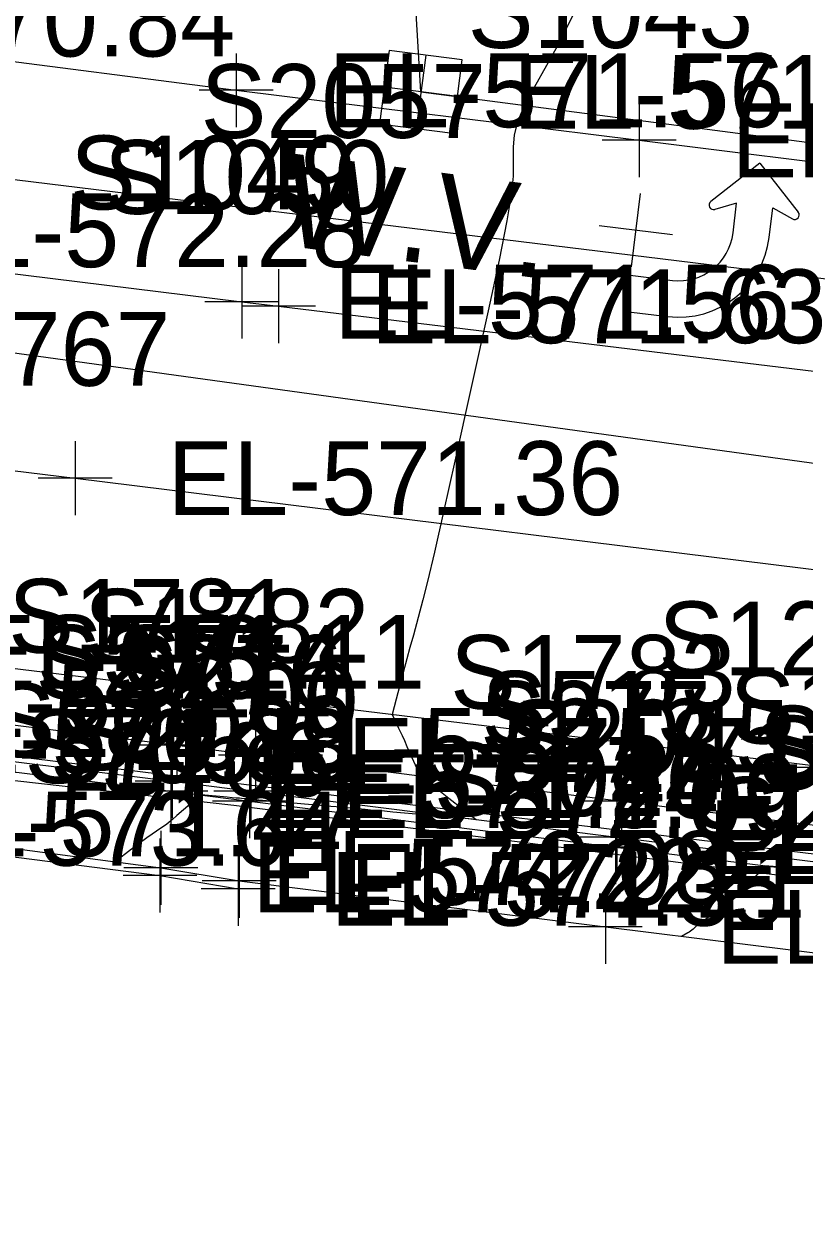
# Model space of a CAD drawing. Extents: x 1724534 to 1727318, y 657156 to 660047.
# Drawn here: x 1725826.2 to 1725868.5, y 658518.4 to 658583.4 of the extents above; entities that cross this region are included whole.
import ezdxf

# ---------------------------------------------------------------- set-up
doc = ezdxf.new("R2010")
doc.units = 0
for name, color, linetype in [('SURVEY - CONTOURS - Intermediate with optional Text', 7, 'Continuous'), ('SURVEY - DRAINAGE - Area Shapes', 7, 'Continuous'), ('SURVEY - DRAINAGE - Storm Sewer', 7, 'Continuous'), ('SURVEY - DRAINAGE - Storm Sewer - Points - Numbers', 7, 'Continuous'), ('SURVEY - DTM - Breaklines', 7, 'Continuous'), ('SURVEY - DTM - Breaklines - Points - Elevations', 7, 'Continuous'), ('SURVEY - DTM - Breaklines - Points - Locators', 7, 'Continuous'), ('SURVEY - DTM - Breaklines - Points - Numbers', 7, 'Continuous'), ('SURVEY - ROADSIDE BARRIERS - Points - Elevations', 7, 'Continuous'), ('SURVEY - ROADSIDE BARRIERS - Points - Locators', 7, 'Continuous'), ('SURVEY - ROADSIDE BARRIERS - Points - Numbers', 7, 'Continuous'), ('SURVEY - ROADSIDE BARRIERS with Text', 7, 'Continuous'), ('SURVEY - TRAFFIC CONTROL - Pavement Marking - Points - Elevations', 7, 'Continuous'), ('SURVEY - TRAFFIC CONTROL - Pavement Marking - Points - Locators', 7, 'Continuous'), ('SURVEY - TRAFFIC CONTROL - Pavement Marking - Points - Numbers', 7, 'Continuous'), ('SURVEY - TRAFFIC CONTROL - Pavement Marking with Text', 7, 'Continuous'), ('SURVEY - TRANSPORTATION - Features', 7, 'Continuous'), ('SURVEY - TRANSPORTATION - Features - Points - Elevations', 7, 'Continuous'), ('SURVEY - TRANSPORTATION - Features - Points - Locators', 7, 'Continuous'), ('SURVEY - TRANSPORTATION - Features - Points - Numbers', 7, 'Continuous'), ('SURVEY - TRANSPORTATION - Roads', 7, 'Continuous'), ('SURVEY - TRANSPORTATION - Roads - Points - Elevations', 7, 'Continuous'), ('SURVEY - TRANSPORTATION - Roads - Points - Locators', 7, 'Continuous'), ('SURVEY - TRANSPORTATION - Roads - Points - Numbers', 7, 'Continuous'), ('SURVEY - UTILITIES - Electric (Underground) with Text', 7, 'Continuous'), ('SURVEY - UTILITIES - Water - Points - Elevations', 7, 'Continuous'), ('SURVEY - UTILITIES - Water - Points - Locators', 7, 'Continuous'), ('SURVEY - UTILITIES - Water with Text', 7, 'Continuous')]:
    doc.layers.add(name, color=color, linetype=linetype)

msp = doc.modelspace()

# ---------------------------------------------------------------- linework, layer by layer
at = {"layer": 'SURVEY - CONTOURS - Intermediate with optional Text'}
for points in [[(1725855.954, 658583.868), (1725855.595, 658583.124), (1725855.203, 658582.364), (1725854.778, 658581.589), (1725853.601, 658579.503), (1725853.215, 658578.743), (1725852.939, 658578.03), (1725852.773, 658577.363), (1725852.717, 658576.741), (1725852.714, 658575.145), (1725852.629, 658574.241), (1725852.375, 658572.723), (1725851.952, 658570.593), (1725851.361, 658567.85), (1725849.559, 658559.717), (1725848.944, 658556.96), (1725848.449, 658554.786), (1725848.076, 658553.196), (1725847.823, 658552.19), (1725847.31, 658550.285), (1725847.128, 658549.606), (1725846.964, 658548.998), (1725846.695, 658547.996), (1725846.155, 658545.991), (1725846.509, 658545.252), (1725846.595, 658545.071), (1725846.699, 658544.844), (1725846.822, 658544.572), (1725846.965, 658544.254), (1725847.672, 658542.666), (1725848.318, 658542.163), (1725848.478, 658542.038), (1725848.684, 658541.878), (1725849.229, 658541.453), (1725850.711, 658540.3), (1725849.502, 658540.407), (1725849.265, 658540.428), (1725849.07, 658540.446), (1725848.811, 658540.469), (1725848.581, 658540.489), (1725848.446, 658540.501), (1725848.214, 658540.522), (1725847.884, 658540.551), (1725846.192, 658540.702), (1725845.743, 658540.742), (1725845.344, 658540.778), (1725844.995, 658540.809), (1725844.698, 658540.836), (1725843.697, 658540.925), (1725843.418, 658540.95), (1725843.134, 658540.976), (1725842.846, 658541.001), (1725842.073, 658541.07), (1725841.409, 658541.13), (1725841.014, 658541.165), (1725840.578, 658541.204), (1725839.359, 658541.314), (1725838.948, 658541.351), (1725838.397, 658541.4), (1725838.257, 658541.413), (1725838.007, 658541.435), (1725837.887, 658541.446), (1725837.715, 658541.461), (1725837.491, 658541.48), (1725837.216, 658541.504), (1725835.808, 658541.627), (1725834.5, 658540.513), (1725834.254, 658540.304), (1725834.079, 658540.154), (1725833.939, 658540.035), (1725833.939, 658540.035), (1725833.91, 658540.015), (1725833.824, 658539.956), (1725833.681, 658539.859), (1725832.871, 658539.305), (1725832.647, 658539.15), (1725832.433, 658538.996), (1725832.228, 658538.845), (1725832.034, 658538.696), (1725831.149, 658538.004), (1725831.129, 658537.971)], [(1725868.725, 658537.589), (1725868.398, 658537.617), (1725868.173, 658537.636), (1725868.049, 658537.646), (1725867.766, 658537.67), (1725867.643, 658537.681), (1725867.485, 658537.694), (1725867.294, 658537.711), (1725866.324, 658537.794), (1725865.387, 658536.685), (1725865.169, 658536.448), (1725864.919, 658536.21), (1725864.636, 658535.973), (1725864.32, 658535.735), (1725863.434, 658535.102), (1725863.135, 658534.887), (1725862.903, 658534.717), (1725862.737, 658534.592), (1725862.639, 658534.512), (1725862.465, 658534.357), (1725862.399, 658534.301), (1725862.331, 658534.25), (1725862.26, 658534.202), (1725862.188, 658534.159), (1725861.845, 658533.968)]]:
    msp.add_lwpolyline(points, dxfattribs=at)
at = {"layer": 'SURVEY - DRAINAGE - Area Shapes'}
msp.add_lwpolyline([(1725876.527, 658537.521), (1725880.453, 658568.253), (1725462.782, 658619.36), (1725459.014, 658588.567)], close=True, dxfattribs=at)
at = {"layer": 'SURVEY - DRAINAGE - Storm Sewer'}
msp.add_lwpolyline([(1725899.594, 658555.371), (1725464.565, 658615.304), (1725129.381, 658652.795)], dxfattribs=at)
at = {"layer": 'SURVEY - DTM - Breaklines'}
msp.add_lwpolyline([(1725680.682, 658560.757), (1725700.532, 658558.327), (1725720.383, 658555.896), (1725740.231, 658553.451), (1725761.261, 658550.794), (1725763.358, 658550.522), (1725772.397, 658549.361), (1725785.767, 658547.812), (1725794.485, 658546.715), (1725814.329, 658544.278), (1725834.171, 658541.836), (1725838.432, 658541.293), (1725858.267, 658538.797), (1725873.4, 658536.913), (1725878.358, 658536.288), (1725898.186, 658533.731), (1725916.254, 658531.264)], dxfattribs=at)
at = {"layer": 'SURVEY - DTM - Breaklines - Points - Locators'}
for p, q in [((1725834.171, 658543.836), (1725834.171, 658539.836)), ((1725838.432, 658543.293), (1725838.432, 658539.293)), ((1725836.171, 658541.836), (1725832.171, 658541.836)), ((1725840.432, 658541.293), (1725836.432, 658541.293)), ((1725858.267, 658540.797), (1725858.267, 658536.797)), ((1725860.267, 658538.797), (1725856.267, 658538.797))]:
    msp.add_line(p, q, dxfattribs=at)
at = {"layer": 'SURVEY - ROADSIDE BARRIERS - Points - Locators'}
for p, q in [((1725833.582, 658539.268), (1725833.582, 658535.268)), ((1725837.82, 658538.545), (1725837.82, 658534.545)), ((1725835.582, 658537.268), (1725831.582, 658537.268)), ((1725839.82, 658536.545), (1725835.82, 658536.545))]:
    msp.add_line(p, q, dxfattribs=at)
at = {"layer": 'SURVEY - ROADSIDE BARRIERS with Text'}
msp.add_lwpolyline([(1725760.694, 658546.317), (1725762.794, 658546.074), (1725771.84, 658544.972), (1725785.195, 658543.377), (1725793.917, 658542.307), (1725813.751, 658539.797), (1725833.582, 658537.268), (1725837.82, 658536.545)], dxfattribs=at)
at = {"layer": 'SURVEY - TRAFFIC CONTROL - Pavement Marking - Points - Locators'}
for p, q in [((1725837.716, 658581.798), (1725837.716, 658577.798)), ((1725839.716, 658579.798), (1725835.716, 658579.798)), ((1725859.541, 658579.092), (1725859.541, 658575.092)), ((1725861.541, 658577.092), (1725857.541, 658577.092)), ((1725859.603, 658574.204), (1725859.117, 658570.234)), ((1725861.345, 658571.976), (1725857.375, 658572.462)), ((1725838.021, 658570.345), (1725838.021, 658566.345)), ((1725840.005, 658570.1), (1725840.005, 658566.1)), ((1725840.021, 658568.345), (1725836.021, 658568.345)), ((1725842.005, 658568.1), (1725838.005, 658568.1)), ((1725828.993, 658560.789), (1725828.993, 658556.789)), ((1725830.993, 658558.789), (1725826.993, 658558.789))]:
    msp.add_line(p, q, dxfattribs=at)
at = {"layer": 'SURVEY - TRAFFIC CONTROL - Pavement Marking with Text'}
for p, q in [((1725866.084, 658575.858), (1725863.423, 658573.777)), ((1725866.084, 658575.858), (1725868.164, 658573.197)), ((1725864.825, 658573.675), (1725863.641, 658573.347)), ((1725864.629, 658572.07), (1725864.825, 658573.675)), ((1725866.582, 658571.831), (1725866.779, 658573.437)), ((1725866.779, 658573.437), (1725867.849, 658572.832)), ((1725859.061, 658569.777), (1725858.822, 658567.824)), ((1725859.061, 658569.777), (1725861.34, 658569.498)), ((1725858.822, 658567.824), (1725861.101, 658567.545))]:
    msp.add_line(p, q, dxfattribs=at)
for points in [[(1725507.893, 658598.435), (1725611.44, 658585.624), (1725663.045, 658579.239), (1725732.511, 658570.646), (1725771.433, 658565.831), (1725828.993, 658558.789), (1725876.604, 658552.91), (1725911.384, 658548.615)], [(1725691.276, 658598.614), (1725717.028, 658595.036), (1725719.009, 658594.766), (1725742.941, 658591.917), (1725766.76, 658588.985), (1725807.969, 658583.629), (1725837.716, 658579.798), (1725859.541, 658577.092), (1725887.31, 658573.624), (1725917.054, 658569.88)], [(1725753.893, 658578.677), (1725768.555, 658576.886), (1725792.375, 658573.977), (1725838.021, 658568.345), (1725840.005, 658568.1), (1725897.548, 658561.116), (1725916.187, 658558.855)]]:
    msp.add_lwpolyline(points, dxfattribs=at)
for centre, radius, start, end in [((1725863.575, 658573.583), 0.246, 128.02638, 285.51954), ((1725867.97, 658573.046), 0.246, 240.57811, 38.02638), ((1725861.699, 658572.429), 4.92, 263.02638, 353.02638), ((1725861.699, 658572.429), 2.952, 263.02638, 353.02638)]:
    msp.add_arc(centre, radius, start, end, dxfattribs=at)
at = {"layer": 'SURVEY - TRANSPORTATION - Features'}
for points in [[(1725680.75, 658561.297), (1725700.601, 658558.867), (1725720.452, 658556.439), (1725740.3, 658553.994), (1725761.33, 658551.338), (1725763.427, 658551.066), (1725772.465, 658549.905), (1725773.017, 658549.841), (1725785.837, 658548.356), (1725794.555, 658547.258), (1725814.399, 658544.822), (1725834.241, 658542.379), (1725838.502, 658541.836), (1725858.338, 658539.34), (1725873.47, 658537.457), (1725878.428, 658536.831), (1725898.256, 658534.275), (1725916.324, 658531.808)], [(1725773.017, 658549.841), (1725772.713, 658551.857), (1725786.089, 658550.308), (1725794.807, 658549.211), (1725814.651, 658546.773), (1725834.493, 658544.331), (1725838.754, 658543.788), (1725858.589, 658541.292), (1725873.721, 658539.408), (1725878.681, 658538.783), (1725898.508, 658536.226), (1725916.581, 658533.801)], [(1725760.676, 658546.181), (1725762.959, 658547.374), (1725771.996, 658546.202), (1725785.261, 658543.884), (1725793.979, 658542.787), (1725813.816, 658540.298), (1725833.635, 658537.675), (1725837.876, 658536.979), (1725857.711, 658534.482), (1725872.844, 658532.599), (1725877.802, 658531.973), (1725897.627, 658529.389), (1725915.695, 658526.927)]]:
    msp.add_lwpolyline(points, dxfattribs=at)
at = {"layer": 'SURVEY - TRANSPORTATION - Features - Points - Locators'}
for p, q in [((1725834.493, 658546.331), (1725834.493, 658542.331)), ((1725838.754, 658545.788), (1725838.754, 658541.788)), ((1725836.493, 658544.331), (1725832.493, 658544.331)), ((1725834.241, 658544.379), (1725834.241, 658540.379)), ((1725840.754, 658543.788), (1725836.754, 658543.788)), ((1725838.502, 658543.836), (1725838.502, 658539.836)), ((1725858.589, 658543.292), (1725858.589, 658539.292)), ((1725836.241, 658542.379), (1725832.241, 658542.379)), ((1725840.502, 658541.836), (1725836.502, 658541.836)), ((1725860.589, 658541.292), (1725856.589, 658541.292)), ((1725858.338, 658541.34), (1725858.338, 658537.34)), ((1725833.635, 658539.675), (1725833.635, 658535.675)), ((1725860.338, 658539.34), (1725856.338, 658539.34)), ((1725837.876, 658538.979), (1725837.876, 658534.979)), ((1725835.635, 658537.675), (1725831.635, 658537.675)), ((1725839.876, 658536.979), (1725835.876, 658536.979)), ((1725857.711, 658536.482), (1725857.711, 658532.482)), ((1725859.711, 658534.482), (1725855.711, 658534.482))]:
    msp.add_line(p, q, dxfattribs=at)
at = {"layer": 'SURVEY - TRANSPORTATION - Roads'}
msp.add_lwpolyline([(1725616.971, 658574.343), (1725730.092, 658560.27), (1725772.626, 658554.978), (1725818.273, 658549.383), (1725869.87, 658543.106), (1725897.655, 658539.757), (1725899.639, 658539.517), (1725928.541, 658535.917)], dxfattribs=at)
at = {"layer": 'SURVEY - TRANSPORTATION - Roads - Points - Locators'}
msp.add_line((1725871.87, 658543.106), (1725867.87, 658543.106), dxfattribs=at)
at = {"layer": 'SURVEY - UTILITIES - Electric (Underground) with Text'}
msp.add_lwpolyline([(1725780.974, 658547.452), (1725837.588, 658541.08), (1725892.762, 658533.99), (1725944.681, 658527.231), (1725958.361, 658525.297), (1725964.566, 658523.411), (1725971.45, 658518.072), (1725975.975, 658512.132)], dxfattribs=at)
at = {"layer": 'SURVEY - UTILITIES - Water - Points - Locators'}
for p, q in [((1725847.98, 658581.696), (1725847.468, 658577.728)), ((1725849.708, 658579.456), (1725845.74, 658579.968))]:
    msp.add_line(p, q, dxfattribs=at)
at = {"layer": 'SURVEY - UTILITIES - Water with Text'}
msp.add_line((1725847.724, 658579.712), (1725847.724, 658579.712), dxfattribs=at)
for points in [[(1725847.724, 658579.712), (1725846.548, 658599.52), (1725380.522, 658660.104)], [(1725845.996, 658581.951), (1725845.485, 658577.984), (1725849.452, 658577.473), (1725849.963, 658581.44), (1725845.996, 658581.951)], [(1725847.724, 658579.712), (1725982.184, 658562.183), (1725988.335, 658559.963), (1726011.571, 658556.88)]]:
    msp.add_lwpolyline(points, dxfattribs=at)

# ---------------------------------------------------------------- texts
at = {"layer": 'SURVEY - DRAINAGE - Storm Sewer - Points - Numbers'}
msp.add_text('S2045', height=4, dxfattribs=at).set_placement((1725852.254, 658542.78))
at = {"layer": 'SURVEY - DTM - Breaklines - Points - Elevations'}
for s, p in [('EL-571.38', (1725819.329, 658542.278)), ('EL-571.94', (1725839.171, 658539.836)), ('EL-572.09', (1725843.432, 658539.293)), ('EL-572.73', (1725863.267, 658536.797))]:
    msp.add_text(s, height=4, dxfattribs=at).set_placement(p)
at = {"layer": 'SURVEY - DTM - Breaklines - Points - Numbers'}
for s, p in [('S275', (1725826.835, 658546.836)), ('S276', (1725830.986, 658546.293)), ('S277', (1725850.931, 658543.797)), ('S278', (1725866.017, 658541.913))]:
    msp.add_text(s, height=4, dxfattribs=at).set_placement(p)
at = {"layer": 'SURVEY - ROADSIDE BARRIERS - Points - Elevations'}
for s, p in [('EL-573.64', (1725818.751, 658537.797)), ('EL-574.22', (1725838.582, 658535.268)), ('EL-574.35', (1725842.82, 658534.545))]:
    msp.add_text(s, height=4, dxfattribs=at).set_placement(p)
at = {"layer": 'SURVEY - ROADSIDE BARRIERS - Points - Numbers'}
for s, p in [('S705', (1725826.246, 658542.268)), ('S706', (1725830.374, 658541.545))]:
    msp.add_text(s, height=4, dxfattribs=at).set_placement(p)
at = {"layer": 'SURVEY - TRAFFIC CONTROL - Pavement Marking - Points - Elevations'}
for s, p in [('EL-570.84', (1725812.969, 658581.629)), ('EL-571.56', (1725842.716, 658577.798)), ('EL-572.20', (1725864.541, 658575.092)), ('EL-572.28', (1725820.075, 658570.219)), ('EL-571.56', (1725843.021, 658566.345)), ('EL-571.63', (1725845.005, 658566.1)), ('EL-571.36', (1725833.993, 658556.789))]:
    msp.add_text(s, height=4, dxfattribs=at).set_placement(p)
at = {"layer": 'SURVEY - TRAFFIC CONTROL - Pavement Marking - Points - Numbers'}
for s, p in [('S1043', (1725850.253, 658582.092)), ('S2057', (1725835.784, 658577.219)), ('S1049', (1725828.718, 658573.345)), ('S1050', (1725830.544, 658573.1)), ('S767', (1725821.657, 658563.789))]:
    msp.add_text(s, height=4, dxfattribs=at).set_placement(p)
at = {"layer": 'SURVEY - TRANSPORTATION - Features - Points - Elevations'}
for s, p in [('EL-571.00', (1725819.651, 658544.773)), ('EL-570.88', (1725819.399, 658542.822)), ('EL-571.58', (1725839.493, 658542.331)), ('EL-571.71', (1725843.754, 658541.788)), ('EL-571.46', (1725839.241, 658540.379)), ('EL-571.60', (1725843.502, 658539.836)), ('EL-572.36', (1725863.589, 658539.292)), ('EL-571.47', (1725819.816, 658538.298)), ('EL-572.25', (1725863.338, 658537.34)), ('EL-572.08', (1725839.635, 658535.675)), ('EL-572.21', (1725843.876, 658534.979)), ('EL-572.89', (1725863.711, 658532.482))]:
    msp.add_text(s, height=4, dxfattribs=at).set_placement(p)
at = {"layer": 'SURVEY - TRANSPORTATION - Features - Points - Numbers'}
for s, p in [('S1781', (1725825.363, 658549.331)), ('S1782', (1725829.466, 658548.788)), ('S513', (1725826.905, 658547.379)), ('S514', (1725831.166, 658546.836)), ('S1783', (1725849.301, 658546.292)), ('S515', (1725851.002, 658544.34)), ('S1784', (1725864.433, 658544.408)), ('S2022', (1725824.347, 658543.675)), ('S2023', (1725828.588, 658542.979)), ('S516', (1725866.024, 658542.457)), ('S2024', (1725848.423, 658540.482)), ('S2025', (1725863.556, 658538.599))]:
    msp.add_text(s, height=4, dxfattribs=at).set_placement(p)
at = {"layer": 'SURVEY - TRANSPORTATION - Roads - Points - Elevations'}
msp.add_text('EL-571.11', height=4, dxfattribs=at).set_placement((1725823.273, 658547.383))
at = {"layer": 'SURVEY - TRANSPORTATION - Roads - Points - Numbers'}
msp.add_text('S1284', height=4, dxfattribs=at).set_placement((1725860.582, 658548.106))
at = {"layer": 'SURVEY - UTILITIES - Water - Points - Elevations'}
msp.add_text('EL-571.98', height=4, dxfattribs=at).set_placement((1725852.724, 658577.712))
at = {"layer": 'SURVEY - UTILITIES - Water with Text'}
msp.add_text('W.V.', height=5.0001, rotation=352.65747, dxfattribs=at).set_placement((1725840.052, 658571.425))

doc.saveas('drawing.dxf')
